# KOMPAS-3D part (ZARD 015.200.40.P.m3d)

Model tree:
1. Плоскость XY
2. Плоскость ZX
3. Плоскость ZY
4. Ось X
5. Ось Y
6. Ось Z
7. Начало координат
8. Смещенная плоскость:1
     Расстояние = 100
9. Смещенная плоскость:2
     Расстояние = 100
10. Булева операция:3
11. Булева операция:4
